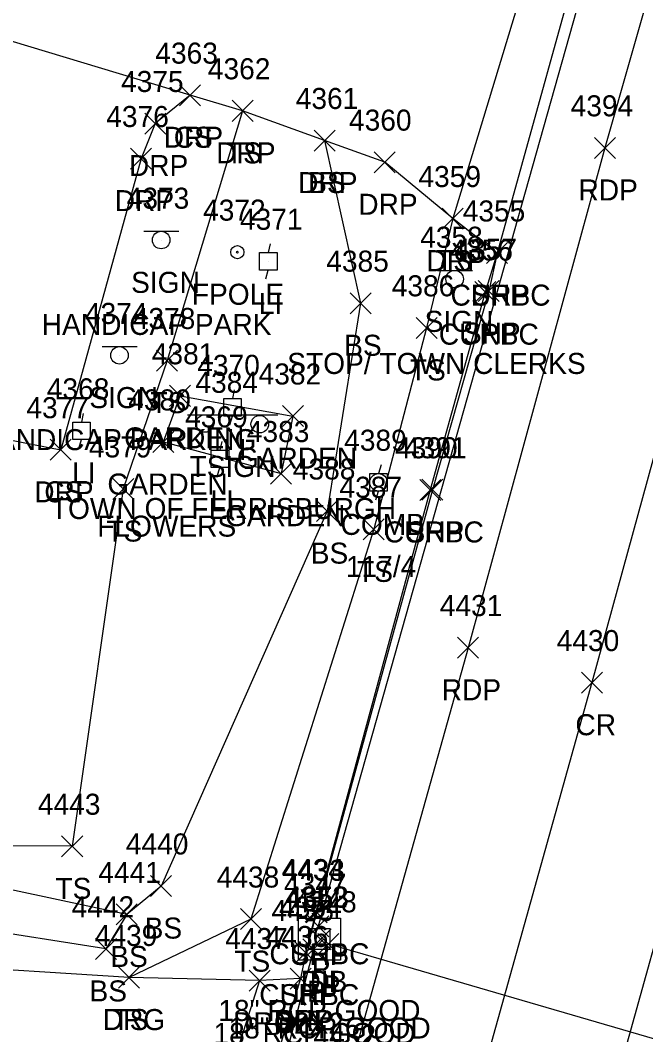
# Model space of a CAD drawing. Extents: x 1443912 to 1445411, y 621446 to 623693.
# Drawn here: x 1444883.7 to 1444943.2, y 623239.1 to 623335.6 of the extents above; entities that cross this region are included whole.
import ezdxf

# ---------------------------------------------------------------- set-up
doc = ezdxf.new("R2010")
doc.units = 0
for name, color, linetype in [('D_A', 7, 'Continuous'), ('D_C', 7, 'Continuous'), ('D_I', 7, 'Continuous'), ('D_TIC', 7, 'Continuous'), ('DCP', 7, 'Continuous'), ('DS', 7, 'Continuous'), ('L_A', 7, 'Continuous'), ('L_C', 7, 'Continuous'), ('L_I', 7, 'Continuous'), ('L_TIC', 7, 'Continuous'), ('LAPB', 7, 'Continuous'), ('LELB', 7, 'Continuous'), ('LFP', 7, 'Continuous'), ('P_A', 7, 'Continuous'), ('P_I', 7, 'Continuous'), ('P_TIC', 7, 'Continuous'), ('PET', 7, 'Continuous'), ('PRC', 7, 'Continuous'), ('PSP', 7, 'Continuous'), ('R_A', 7, 'Continuous'), ('R_I', 7, 'Continuous'), ('R_TIC', 7, 'Continuous'), ('RC', 7, 'Continuous'), ('RDG', 7, 'Continuous'), ('RDP', 7, 'Continuous'), ('S_A', 7, 'Continuous'), ('S_C', 7, 'Continuous'), ('S_I', 7, 'Continuous'), ('SSGN', 7, 'Continuous'), ('U_A', 7, 'Continuous'), ('U_C', 7, 'Continuous'), ('U_I', 7, 'Continuous'), ('ULP', 7, 'Continuous'), ('UP', 7, 'Continuous')]:
    doc.layers.add(name, color=color, linetype=linetype)

msp = doc.modelspace()

# ---------------------------------------------------------------- linework, layer by layer
at = {"layer": 'D_TIC'}
for points in [[(1444911.023, 623248.417), (1444913.023, 623250.417)], [(1444913.023, 623248.417), (1444911.023, 623250.417)], [(1444911.241, 623247.186), (1444913.241, 623249.186)], [(1444913.241, 623247.186), (1444911.241, 623249.186)], [(1444910.563, 623246.238), (1444912.563, 623248.238)], [(1444912.563, 623246.238), (1444910.563, 623248.238)], [(1444911.99, 623246.747), (1444913.99, 623248.747)], [(1444913.99, 623246.747), (1444911.99, 623248.747)]]:
    msp.add_lwpolyline(points, dxfattribs=at)
at = {"layer": 'DCP'}
for points in [[(1444941.738, 623354.888), (1444912.023, 623249.417)], [(1444911.563, 623247.238), (1444894.245, 623180.504)], [(1444912.99, 623247.747), (1444947.257, 623237.76)]]:
    msp.add_lwpolyline(points, dxfattribs=at)
at = {"layer": 'DS'}
for p, q in [((1444910.135, 623250.206), (1444914.135, 623250.206)), ((1444910.135, 623246.206), (1444910.135, 623250.206)), ((1444914.135, 623250.206), (1444914.135, 623246.206)), ((1444911.135, 623247.206), (1444911.135, 623249.206)), ((1444911.135, 623249.206), (1444913.135, 623249.206)), ((1444913.135, 623249.206), (1444913.135, 623247.206)), ((1444912.14, 623248.208), (1444912.14, 623248.208)), ((1444912.14, 623248.208), (1444912.14, 623248.208)), ((1444913.135, 623247.206), (1444911.135, 623247.206)), ((1444914.135, 623246.206), (1444910.135, 623246.206))]:
    msp.add_line(p, q, dxfattribs=at)
at = {"layer": 'L_TIC'}
for points in [[(1444898.838, 623327.442), (1444900.838, 623329.442)], [(1444900.838, 623327.442), (1444898.838, 623329.442)], [(1444903.831, 623325.954), (1444905.831, 623327.954)], [(1444905.831, 623325.954), (1444903.831, 623327.954)], [(1444911.624, 623323.13), (1444913.624, 623325.13)], [(1444913.624, 623323.13), (1444911.624, 623325.13)], [(1444923.82, 623315.707), (1444925.82, 623317.707)], [(1444925.82, 623315.707), (1444923.82, 623317.707)], [(1444915.045, 623307.663), (1444917.045, 623309.663)], [(1444917.045, 623307.663), (1444915.045, 623309.663)], [(1444921.327, 623305.318), (1444923.327, 623307.318)], [(1444923.327, 623305.318), (1444921.327, 623307.318)], [(1444896.644, 623302.209), (1444898.644, 623304.209)], [(1444898.644, 623302.209), (1444896.644, 623304.209)], [(1444897.886, 623298.854), (1444899.886, 623300.854)], [(1444899.886, 623298.854), (1444897.886, 623300.854)], [(1444908.611, 623296.935), (1444910.611, 623298.935)], [(1444910.611, 623296.935), (1444908.611, 623298.935)], [(1444896.3, 623294.467), (1444898.3, 623296.467)], [(1444898.3, 623294.467), (1444896.3, 623296.467)], [(1444896.3, 623294.467), (1444898.3, 623296.467)], [(1444898.3, 623294.467), (1444896.3, 623296.467)], [(1444886.528, 623293.73), (1444888.528, 623295.73)], [(1444888.528, 623293.73), (1444886.528, 623295.73)], [(1444907.493, 623291.46), (1444909.493, 623293.46)], [(1444909.493, 623291.46), (1444907.493, 623293.46)], [(1444907.493, 623291.46), (1444909.493, 623293.46)], [(1444909.493, 623291.46), (1444907.493, 623293.46)], [(1444892.476, 623289.997), (1444894.476, 623291.997)], [(1444894.476, 623289.997), (1444892.476, 623291.997)], [(1444911.868, 623287.9), (1444913.868, 623289.9)], [(1444913.868, 623287.9), (1444911.868, 623289.9)], [(1444916.3, 623286.164), (1444918.3, 623288.164)], [(1444918.3, 623286.164), (1444916.3, 623288.164)], [(1444887.62, 623256.022), (1444889.62, 623258.022)], [(1444889.62, 623256.022), (1444887.62, 623258.022)], [(1444896.071, 623252.248), (1444898.071, 623254.248)], [(1444898.071, 623252.248), (1444896.071, 623254.248)], [(1444892.804, 623249.546), (1444894.804, 623251.546)], [(1444894.804, 623249.546), (1444892.804, 623251.546)], [(1444892.804, 623249.546), (1444894.804, 623251.546)], [(1444894.804, 623249.546), (1444892.804, 623251.546)], [(1444904.628, 623249.101), (1444906.628, 623251.101)], [(1444906.628, 623249.101), (1444904.628, 623251.101)], [(1444890.827, 623246.272), (1444892.827, 623248.272)], [(1444892.827, 623246.272), (1444890.827, 623248.272)], [(1444893.039, 623243.548), (1444895.039, 623245.548)], [(1444895.039, 623243.548), (1444893.039, 623245.548)]]:
    msp.add_lwpolyline(points, dxfattribs=at)
at = {"layer": 'LAPB'}
for points in [[(1444897.3, 623295.467), (1444898.886, 623299.854), (1444909.611, 623297.935), (1444908.493, 623292.46)], [(1444897.3, 623295.467), (1444908.493, 623292.46)]]:
    msp.add_lwpolyline(points, dxfattribs=at)
at = {"layer": 'LELB'}
for points in [[(1444939.345, 623351.652), (1444933.904, 623346.605), (1444924.82, 623316.707), (1444922.327, 623306.318), (1444917.3, 623287.164), (1444905.628, 623250.101), (1444894.039, 623244.548)], [(1444899.838, 623328.442), (1444881.011, 623334.123), (1444859.605, 623341.032), (1444849.839, 623302.329), (1444870.76, 623297.973), (1444887.528, 623294.73)], [(1444904.831, 623326.954), (1444897.644, 623303.209), (1444893.476, 623290.997), (1444888.62, 623257.022), (1444879.216, 623257.077), (1444868.954, 623258.668), (1444848.912, 623262.875)], [(1444912.624, 623324.13), (1444916.045, 623308.663), (1444912.868, 623288.9), (1444897.071, 623253.248), (1444893.804, 623250.546), (1444891.827, 623247.272), (1444878.881, 623249.308), (1444868.691, 623253.363), (1444847.94, 623252.765)], [(1444893.804, 623250.546), (1444879.852, 623253.516), (1444868.958, 623255.023), (1444848.496, 623259.283)]]:
    msp.add_lwpolyline(points, dxfattribs=at)
at = {"layer": 'LFP'}
for radius in [0.625, 0.0833]:
    msp.add_circle((1444904.33, 623313.514), radius, dxfattribs=at)
at = {"layer": 'P_TIC'}
for points in [[(1444938.286, 623322.432), (1444940.286, 623324.432)], [(1444940.286, 623322.432), (1444938.286, 623324.432)], [(1444928.025, 623312.433), (1444930.025, 623314.433)], [(1444930.025, 623312.433), (1444928.025, 623314.433)], [(1444927.238, 623308.81), (1444929.238, 623310.81)], [(1444929.238, 623308.81), (1444927.238, 623310.81)], [(1444921.874, 623289.92), (1444923.874, 623291.92)], [(1444923.874, 623289.92), (1444921.874, 623291.92)], [(1444925.274, 623274.909), (1444927.274, 623276.909)], [(1444927.274, 623274.909), (1444925.274, 623276.909)], [(1444937.047, 623271.584), (1444939.047, 623273.584)], [(1444939.047, 623271.584), (1444937.047, 623273.584)], [(1444910.871, 623249.743), (1444912.871, 623251.743)], [(1444912.871, 623249.743), (1444910.871, 623251.743)], [(1444909.828, 623245.919), (1444911.828, 623247.919)], [(1444911.828, 623245.919), (1444909.828, 623247.919)], [(1444909.341, 623243.449), (1444911.341, 623245.449)], [(1444911.341, 623243.449), (1444909.341, 623245.449)]]:
    msp.add_lwpolyline(points, dxfattribs=at)
at = {"layer": 'PET'}
for points in [[(1445036.702, 623677.704), (1445026.384, 623639.781), (1445008.648, 623576.155), (1444996.948, 623532.888), (1444979.777, 623472.466), (1444964.829, 623416.219), (1444955.709, 623382.545), (1444949.165, 623358.134), (1444939.286, 623323.432), (1444926.274, 623275.909), (1444914.827, 623235.039), (1444901.528, 623186.461), (1444892.14, 623152.692), (1444883.143, 623119.129), (1444870.129, 623073.226), (1444861.494, 623043.31), (1444850.844, 623006.823), (1444834.615, 622954.828), (1444817.277, 622898.327)], [(1445060.037, 623670.522), (1445049.49, 623631.423), (1445031.605, 623567.438), (1445020.437, 623527.05), (1445003.496, 623465.591), (1444988.101, 623409.137), (1444976.63, 623367.032), (1444962.485, 623315.052), (1444949.489, 623267.355), (1444937.78, 623225.39), (1444926.085, 623182.222), (1444915.481, 623145.054), (1444906.981, 623113.479), (1444893.635, 623066.096), (1444886.059, 623037.306), (1444876.58, 623001.084), (1444863.334, 622947.053), (1444849.426, 622890.74)]]:
    msp.add_lwpolyline(points, dxfattribs=at)
at = {"layer": 'PRC'}
msp.add_lwpolyline([(1445048.115, 623674.07), (1445038.049, 623635.877), (1445020.141, 623572.701), (1445008.5, 623529.106), (1444991.68, 623469.746), (1444976.214, 623412.438), (1444964.866, 623369.69), (1444950.638, 623318.466), (1444938.047, 623272.584), (1444925.386, 623227.302), (1444913.851, 623184.574), (1444903.742, 623148.669), (1444894.967, 623116.182), (1444881.802, 623068.916), (1444873.968, 623040.251), (1444864.099, 623005.335), (1444846.729, 622950.738), (1444829.368, 622896.11)], dxfattribs=at)
at = {"layer": 'PSP'}
msp.add_lwpolyline([(1444938.45, 623347.365), (1444929.025, 623313.433), (1444928.238, 623309.81), (1444922.874, 623290.92), (1444911.871, 623250.743), (1444910.828, 623246.919), (1444910.341, 623244.449), (1444906.243, 623230.997), (1444905.229, 623226.669), (1444898.903, 623204.12), (1444894.62, 623188.308), (1444891.502, 623176.899), (1444890.541, 623173.344), (1444886.055, 623157.557), (1444885.108, 623153.679), (1444881.771, 623141.713), (1444880.574, 623137.991), (1444874.863, 623117.344), (1444874.119, 623114.36), (1444864.329, 623079.142), (1444854.722, 623044.471)], dxfattribs=at)
at = {"layer": 'R_TIC'}
for points in [[(1444898.838, 623327.442), (1444900.838, 623329.442)], [(1444900.838, 623327.442), (1444898.838, 623329.442)], [(1444903.831, 623325.954), (1444905.831, 623327.954)], [(1444905.831, 623325.954), (1444903.831, 623327.954)], [(1444895.53, 623324.748), (1444897.53, 623326.748)], [(1444897.53, 623324.748), (1444895.53, 623326.748)], [(1444911.624, 623323.13), (1444913.624, 623325.13)], [(1444913.624, 623323.13), (1444911.624, 623325.13)], [(1444894.18, 623321.415), (1444896.18, 623323.415)], [(1444896.18, 623321.415), (1444894.18, 623323.415)], [(1444917.342, 623321.07), (1444919.342, 623323.07)], [(1444919.342, 623321.07), (1444917.342, 623323.07)], [(1444923.82, 623315.707), (1444925.82, 623317.707)], [(1444925.82, 623315.707), (1444923.82, 623317.707)], [(1444928.025, 623312.433), (1444930.025, 623314.433)], [(1444930.025, 623312.433), (1444928.025, 623314.433)], [(1444928.025, 623312.433), (1444930.025, 623314.433)], [(1444930.025, 623312.433), (1444928.025, 623314.433)], [(1444926.906, 623308.719), (1444928.906, 623310.719)], [(1444928.906, 623308.719), (1444926.906, 623310.719)], [(1444886.528, 623293.73), (1444888.528, 623295.73)], [(1444888.528, 623293.73), (1444886.528, 623295.73)], [(1444921.677, 623289.914), (1444923.677, 623291.914)], [(1444923.677, 623289.914), (1444921.677, 623291.914)], [(1444910.793, 623249.807), (1444912.793, 623251.807)], [(1444912.793, 623249.807), (1444910.793, 623251.807)], [(1444909.828, 623245.919), (1444911.828, 623247.919)], [(1444911.828, 623245.919), (1444909.828, 623247.919)], [(1444893.039, 623243.548), (1444895.039, 623245.548)], [(1444895.039, 623243.548), (1444893.039, 623245.548)], [(1444905.44, 623243.251), (1444907.44, 623245.251)], [(1444907.44, 623243.251), (1444905.44, 623245.251)], [(1444905.44, 623243.251), (1444907.44, 623245.251)], [(1444907.44, 623243.251), (1444905.44, 623245.251)], [(1444909.341, 623243.449), (1444911.341, 623245.449)], [(1444911.341, 623243.449), (1444909.341, 623245.449)]]:
    msp.add_lwpolyline(points, dxfattribs=at)
at = {"layer": 'RC'}
msp.add_lwpolyline([(1444929.025, 623313.433), (1444927.906, 623309.719), (1444922.677, 623290.914), (1444911.793, 623250.807), (1444910.828, 623246.919)], dxfattribs=at)
at = {"layer": 'RDG'}
msp.add_lwpolyline([(1444906.44, 623244.251), (1444894.039, 623244.548), (1444874.969, 623245.746), (1444868.306, 623251.263), (1444849.514, 623247.129), (1444843.726, 623243.768)], dxfattribs=at)
at = {"layer": 'RDP'}
for points in [[(1444929.025, 623313.433), (1444924.82, 623316.707), (1444918.342, 623322.07), (1444912.624, 623324.13), (1444904.831, 623326.954), (1444899.838, 623328.442), (1444896.53, 623325.748), (1444895.18, 623322.415), (1444887.528, 623294.73)], [(1444910.341, 623244.449), (1444906.44, 623244.251), (1444902.957, 623233.286), (1444906.243, 623230.997)]]:
    msp.add_lwpolyline(points, dxfattribs=at)
at = {"layer": 'SSGN'}
for p, q in [((1444895.44, 623315.5), (1444898.773, 623315.5)), ((1444897.087, 623314.666), (1444897.087, 623314.666)), ((1444923.352, 623311.788), (1444926.685, 623311.788)), ((1444924.998, 623310.955), (1444924.998, 623310.955)), ((1444891.469, 623304.544), (1444894.803, 623304.544)), ((1444893.116, 623303.71), (1444893.116, 623303.71)), ((1444899.585, 623298.061), (1444908.182, 623298.061)), ((1444903.607, 623297.157), (1444903.607, 623297.157))]:
    msp.add_line(p, q, dxfattribs=at)
for centre in [(1444897.087, 623314.666), (1444924.998, 623310.955), (1444893.116, 623303.71), (1444901.246, 623297.228), (1444906.461, 623297.158)]:
    msp.add_circle(centre, 0.833, dxfattribs=at)
at = {"layer": 'ULP'}
for p, q in [((1444907.439, 623314.311), (1444907.273, 623313.478)), ((1444906.439, 623311.811), (1444906.439, 623313.478)), ((1444906.439, 623313.478), (1444908.106, 623313.478)), ((1444907.273, 623312.645), (1444907.273, 623312.645)), ((1444908.106, 623313.478), (1444908.106, 623311.811)), ((1444908.106, 623311.811), (1444906.439, 623311.811)), ((1444907.023, 623310.978), (1444907.273, 623311.811)), ((1444904.032, 623300.421), (1444903.865, 623299.588)), ((1444903.032, 623297.921), (1444903.032, 623299.588)), ((1444903.032, 623299.588), (1444904.698, 623299.588)), ((1444904.698, 623299.588), (1444904.698, 623297.921)), ((1444889.68, 623298.188), (1444889.513, 623297.354)), ((1444903.865, 623298.754), (1444903.865, 623298.754)), ((1444888.68, 623295.688), (1444888.68, 623297.354)), ((1444888.68, 623297.354), (1444890.347, 623297.354)), ((1444890.347, 623297.354), (1444890.347, 623295.688)), ((1444904.698, 623297.921), (1444903.032, 623297.921)), ((1444903.615, 623297.088), (1444903.865, 623297.921)), ((1444889.513, 623296.521), (1444889.513, 623296.521)), ((1444890.347, 623295.688), (1444888.68, 623295.688)), ((1444889.263, 623294.854), (1444889.513, 623295.688)), ((1444902.842, 623295.527), (1444902.676, 623294.693)), ((1444901.842, 623293.027), (1444901.842, 623294.693)), ((1444901.842, 623294.693), (1444903.509, 623294.693)), ((1444903.509, 623294.693), (1444903.509, 623293.027)), ((1444902.676, 623293.86), (1444902.676, 623293.86)), ((1444903.509, 623293.027), (1444901.842, 623293.027)), ((1444902.426, 623292.193), (1444902.676, 623293.027))]:
    msp.add_line(p, q, dxfattribs=at)
at = {"layer": 'UP'}
for p, q in [((1444918.007, 623293.3), (1444917.757, 623292.467)), ((1444916.924, 623290.8), (1444916.924, 623292.467)), ((1444916.924, 623292.467), (1444918.591, 623292.467)), ((1444918.591, 623292.467), (1444918.591, 623290.8)), ((1444917.757, 623291.633), (1444917.757, 623291.633)), ((1444918.591, 623290.8), (1444916.924, 623290.8)), ((1444917.507, 623289.967), (1444917.757, 623290.8))]:
    msp.add_line(p, q, dxfattribs=at)
msp.add_circle((1444917.757, 623291.633), 0.833, dxfattribs=at)

# ---------------------------------------------------------------- texts
at = {"layer": 'D_A'}
for s, p in [('P', (1444911.401, 623244.417)), ('DIB', (1444910.344, 623243.186)), ('DI', (1444911.195, 623243.208)), ('P', (1444910.941, 623242.238)), ('P', (1444912.368, 623242.747))]:
    msp.add_text(s, height=2, dxfattribs=at).set_placement(p)
at = {"layer": 'D_C'}
for s, p in [('18" RCP GOOD', (1444902.519, 623240.417)), ('2X2', (1444909.715, 623239.208)), ('18" RCP GOOD', (1444902.06, 623238.238)), ('18" RCP GOOD', (1444903.487, 623238.747))]:
    msp.add_text(s, height=2, dxfattribs=at).set_placement(p)
at = {"layer": 'D_I'}
for s, p in [('4347', (1444908.763, 623252.417)), ('4352', (1444908.88, 623251.208)), ('4353', (1444908.982, 623251.186)), ('4348', (1444909.731, 623250.747)), ('4354', (1444908.304, 623250.238))]:
    msp.add_text(s, height=2, dxfattribs=at).set_placement(p)
at = {"layer": 'L_A'}
for s, p in [('CS', (1444898.279, 623323.442)), ('TS', (1444903.24, 623321.954)), ('BS', (1444911.065, 623319.13)), ('TS', (1444923.229, 623311.707)), ('FPOLE', (1444900, 623308.514)), ('BS', (1444914.485, 623303.663)), ('TS', (1444920.737, 623301.318)), ('TS', (1444896.053, 623298.209)), ('GARDEN', (1444893.555, 623294.854)), ('GARDEN', (1444904.281, 623292.935)), ('GARDEN', (1444891.97, 623290.467)), ('GARDEN', (1444891.97, 623290.467)), ('CS', (1444885.969, 623289.73)), ('GARDEN', (1444903.162, 623287.46)), ('GARDEN', (1444903.162, 623287.46)), ('TS', (1444891.886, 623285.997)), ('BS', (1444911.308, 623283.9)), ('TS', (1444915.709, 623282.164)), ('TS', (1444887.03, 623252.022)), ('BS', (1444895.512, 623248.248)), ('BS', (1444892.245, 623245.546)), ('BS', (1444892.245, 623245.546)), ('TS', (1444904.038, 623245.101)), ('BS', (1444890.268, 623242.272)), ('TS', (1444892.448, 623239.548))]:
    msp.add_text(s, height=2, dxfattribs=at).set_placement(p)
at = {"layer": 'L_C'}
msp.add_text('FLOWERS', height=2, dxfattribs=at).set_placement((1444891.001, 623286.467))
msp.add_text('FLOWERS', height=2, dxfattribs=at).set_placement((1444891.001, 623286.467))
at = {"layer": 'L_I'}
for s, p in [('4363', (1444896.531, 623331.442)), ('4362', (1444901.524, 623329.954)), ('4361', (1444909.884, 623327.13)), ('4359', (1444921.552, 623319.707)), ('4372', (1444901.07, 623316.514)), ('4385', (1444912.785, 623311.663)), ('4386', (1444919.012, 623309.318)), ('4378', (1444894.384, 623306.209)), ('4381', (1444896.193, 623302.854)), ('4382', (1444906.352, 623300.935)), ('4380', (1444893.954, 623298.467)), ('4380', (1444893.954, 623298.467)), ('4377', (1444884.268, 623297.73)), ('4383', (1444905.233, 623295.46)), ('4383', (1444905.233, 623295.46)), ('4379', (1444890.209, 623293.997)), ('4388', (1444909.608, 623291.9)), ('4387', (1444914.04, 623290.164)), ('4443', (1444885.361, 623260.022)), ('4440', (1444893.725, 623256.248)), ('4441', (1444891.111, 623253.546)), ('4441', (1444891.111, 623253.546)), ('4438', (1444902.368, 623253.101)), ('4442', (1444888.567, 623250.272)), ('4439', (1444890.771, 623247.548))]:
    msp.add_text(s, height=2, dxfattribs=at).set_placement(p)
at = {"layer": 'P_A'}
for s, p in [('RDP', (1444936.774, 623318.432)), ('SHP', (1444926.561, 623308.433)), ('SHP', (1444925.773, 623304.81)), ('SHP', (1444920.41, 623285.92)), ('RDP', (1444923.762, 623270.909)), ('CR', (1444936.48, 623267.584)), ('SHP', (1444909.406, 623245.743)), ('SHP', (1444908.363, 623241.919)), ('SHP', (1444907.876, 623239.449))]:
    msp.add_text(s, height=2, dxfattribs=at).set_placement(p)
at = {"layer": 'P_I'}
for s, p in [('4394', (1444936.026, 623326.432)), ('4355', (1444925.765, 623316.433)), ('4357', (1444924.978, 623312.81)), ('4391', (1444920.182, 623293.92)), ('4431', (1444923.581, 623278.909)), ('4430', (1444934.701, 623275.584)), ('4433', (1444908.611, 623253.743)), ('4435', (1444907.568, 623249.919)), ('4436', (1444907.026, 623247.449)), ('4432', (1444911.567, 623238.039))]:
    msp.add_text(s, height=2, dxfattribs=at).set_placement(p)
at = {"layer": 'R_A'}
for s, p in [('DRP', (1444897.327, 623323.442)), ('DRP', (1444902.319, 623321.954)), ('DRP', (1444894.018, 623320.748)), ('DRP', (1444910.112, 623319.13)), ('DRP', (1444892.668, 623317.415)), ('DRP', (1444915.83, 623317.07)), ('DRP', (1444922.308, 623311.707)), ('CURBC', (1444924.608, 623308.433)), ('DRP', (1444926.513, 623308.433)), ('CURBC', (1444923.489, 623304.719)), ('DRP', (1444885.016, 623289.73)), ('CURBC', (1444918.26, 623285.914)), ('CURBC', (1444907.376, 623245.807)), ('CURBC', (1444906.41, 623241.919)), ('DRG', (1444891.527, 623239.548)), ('DRG', (1444903.928, 623239.251)), ('DRP', (1444903.928, 623239.251)), ('DRP', (1444907.829, 623239.449))]:
    msp.add_text(s, height=2, dxfattribs=at).set_placement(p)
at = {"layer": 'R_I'}
for s, p in [('4363', (1444896.531, 623331.442)), ('4362', (1444901.524, 623329.954)), ('4375', (1444893.271, 623328.748)), ('4361', (1444909.884, 623327.13)), ('4376', (1444891.865, 623325.415)), ('4360', (1444914.948, 623325.07)), ('4359', (1444921.552, 623319.707)), ('4355', (1444925.765, 623316.433)), ('4355', (1444925.765, 623316.433)), ('4356', (1444924.591, 623312.719)), ('4377', (1444884.268, 623297.73)), ('4390', (1444919.331, 623293.914)), ('4434', (1444908.534, 623253.807)), ('4435', (1444907.568, 623249.919)), ('4439', (1444890.771, 623247.548)), ('4437', (1444903.18, 623247.251)), ('4437', (1444903.18, 623247.251)), ('4436', (1444907.026, 623247.449))]:
    msp.add_text(s, height=2, dxfattribs=at).set_placement(p)
at = {"layer": 'S_A'}
for s, p in [('SIGN', (1444894.225, 623309.646)), ('SIGN', (1444922.136, 623305.935)), ('SIGN', (1444890.254, 623298.69)), ('TSIGN', (1444899.783, 623292.14))]:
    msp.add_text(s, height=2, dxfattribs=at).set_placement(p)
at = {"layer": 'S_C'}
for s, p in [('HANDICAP PARK', (1444885.729, 623305.646)), ('STOP/ TOWN CLERKS', (1444909.074, 623301.935)), ('HANDICAP PARKING', (1444879.53, 623294.69)), ('TOWN OF FERRISBURGH', (1444886.594, 623288.14))]:
    msp.add_text(s, height=2, dxfattribs=at).set_placement(p)
at = {"layer": 'S_I'}
for s, p in [('4373', (1444893.807, 623317.646)), ('4358', (1444921.719, 623313.935)), ('4374', (1444889.837, 623306.69)), ('4384', (1444900.342, 623300.14))]:
    msp.add_text(s, height=2, dxfattribs=at).set_placement(p)
at = {"layer": 'U_A'}
for s, p in [('LI', (1444906.375, 623307.645)), ('LI', (1444902.968, 623293.754)), ('LI', (1444888.616, 623291.521)), ('LI', (1444901.778, 623288.86)), ('COMB', (1444914.143, 623286.633))]:
    msp.add_text(s, height=2, dxfattribs=at).set_placement(p)
at = {"layer": 'U_C'}
msp.add_text('117/4', height=2, dxfattribs=at).set_placement((1444914.655, 623282.633))
at = {"layer": 'U_I'}
for s, p in [('4371', (1444904.58, 623315.645)), ('4370', (1444900.519, 623301.754)), ('4368', (1444886.206, 623299.521)), ('4369', (1444899.361, 623296.86)), ('4389', (1444914.49, 623294.633))]:
    msp.add_text(s, height=2, dxfattribs=at).set_placement(p)

doc.saveas('drawing.dxf')
